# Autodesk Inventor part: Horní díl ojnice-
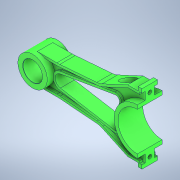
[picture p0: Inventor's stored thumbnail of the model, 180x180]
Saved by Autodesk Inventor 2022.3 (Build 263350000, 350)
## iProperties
Created: 2025-11
Part Number: Horní díl ojnice-
Material: Všeobecné
Description: STEP AP214
Document SubType Name: Modeling
Designer: Hra42
Density: 1 g/cm^3
Appearance: Výchozí
Sending System: SolidWorks 2024
Preprocessor: SwSTEP 2.0
Title: Horní díl ojnice.STEP
Revision Number: LIBOVOLNÃ
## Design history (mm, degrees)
feature "Horní díl ojnice.ipt_1_"
node "Těleso1"
